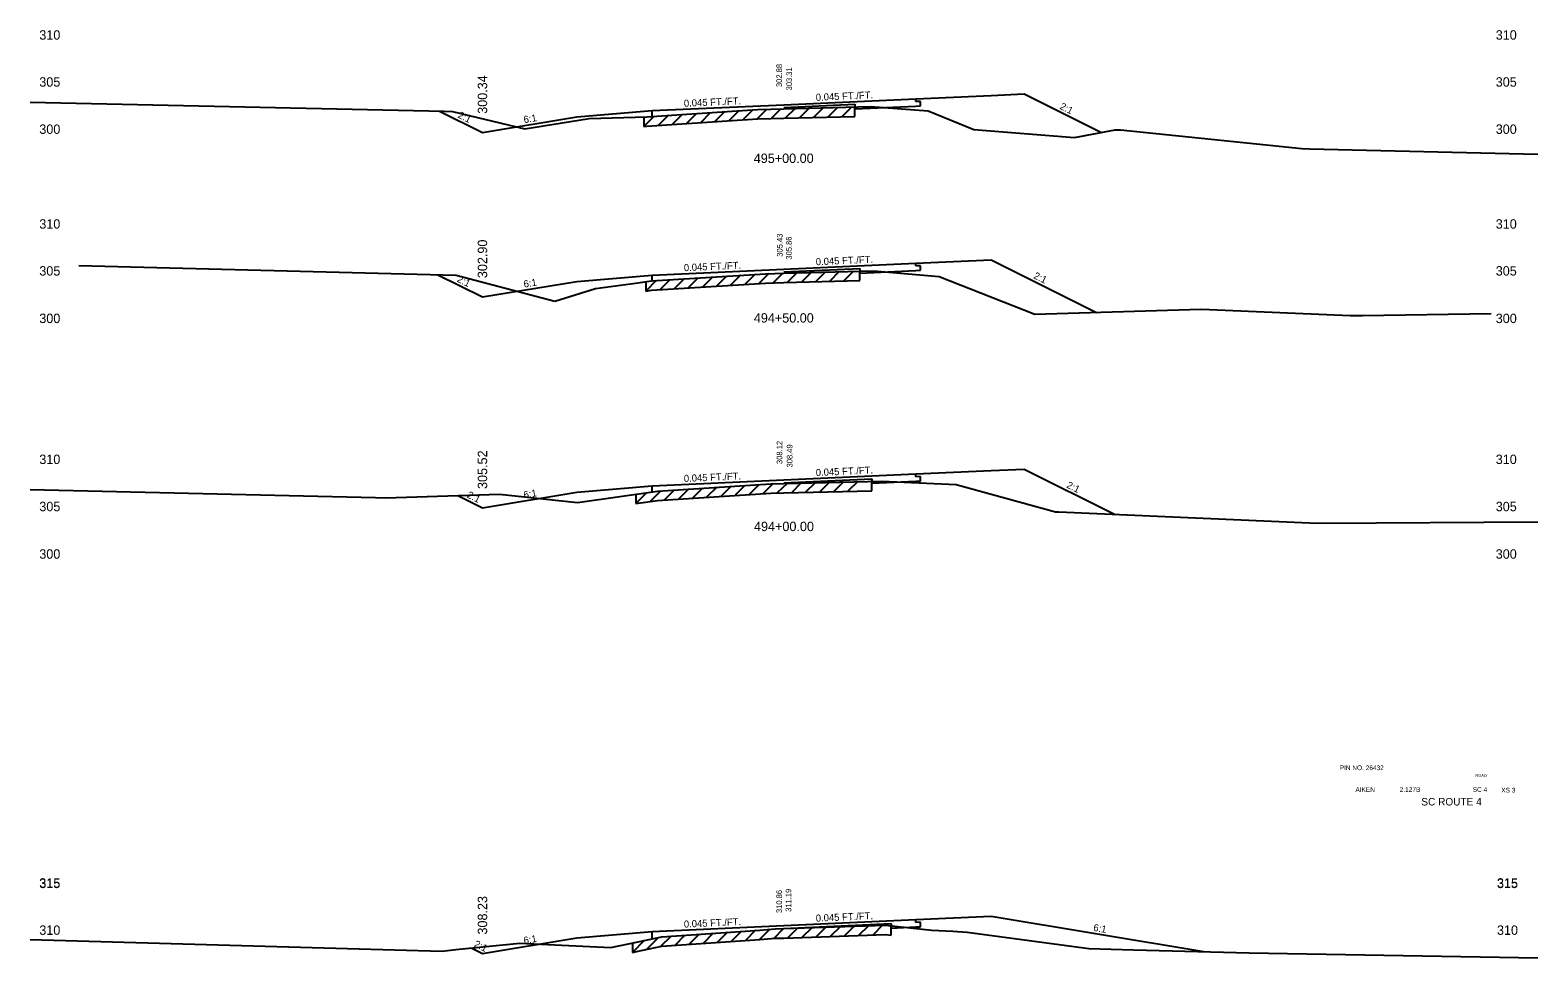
# Model space of a CAD drawing. Extents: x 883 to 1160, y 1002 to 4323.
# Drawn here: x 1000 to 1160, y 1312.8 to 1411.2 of the extents above; entities that cross this region are included whole.
import ezdxf

# ---------------------------------------------------------------- set-up
doc = ezdxf.new("R2010")
doc.units = 0
for name, color, linetype in [('Level 1', 7, 'Continuous'), ('Level 10', 7, 'Continuous'), ('Level 11', 7, 'Continuous'), ('Level 12', 7, 'Continuous'), ('Level 3', 7, 'Continuous'), ('Level 32', 7, 'Continuous'), ('Level 33', 7, 'Continuous'), ('Level 53', 7, 'Continuous'), ('Level 59', 7, 'Continuous'), ('Level 6', 7, 'Continuous'), ('Level 60', 7, 'Continuous'), ('Level 61', 7, 'Continuous'), ('Level 7', 7, 'Continuous')]:
    doc.layers.add(name, color=color, linetype=linetype)

msp = doc.modelspace()

# ---------------------------------------------------------------- linework, layer by layer
at = {"layer": 'Level 11'}
for p, q in [((1094, 1403.64), (1094, 1403.94)), ((1094.5, 1403.66), (1094, 1403.64)), ((1094.5, 1403.18), (1094.5, 1403.66)), ((1066, 1402.06), (1066, 1402.68)), ((1094, 1403.16), (1094.5, 1403.18)), ((1094, 1386.19), (1094, 1386.49)), ((1094.5, 1386.21), (1094, 1386.19)), ((1094, 1385.71), (1094.5, 1385.73)), ((1094.5, 1385.73), (1094.5, 1386.21)), ((1066, 1384.61), (1066, 1385.23)), ((1094, 1363.82), (1094, 1364.12)), ((1094.5, 1363.84), (1094, 1363.82)), ((1094, 1363.34), (1094.5, 1363.36)), ((1094.5, 1363.36), (1094.5, 1363.84)), ((1066, 1362.21), (1066, 1362.86)), ((1094, 1316.52), (1094, 1316.82)), ((1066, 1314.77), (1066, 1315.56)), ((1094.5, 1316.54), (1094, 1316.52)), ((1094, 1316.04), (1094.5, 1316.06)), ((1094.5, 1316.06), (1094.5, 1316.54))]:
    msp.add_line(p, q, dxfattribs=at)
at = {"layer": 'Level 12'}
for p, q in [((1087.51, 1402.87), (1094, 1403.16)), ((1087.51, 1403.07), (1087.51, 1402.87)), ((1088.03, 1385.44), (1094, 1385.71)), ((1088.03, 1385.65), (1088.03, 1385.44)), ((1089.31, 1363.34), (1089.31, 1363.13)), ((1089.31, 1363.13), (1094, 1363.34)), ((1091.36, 1316.16), (1091.36, 1315.92)), ((1091.36, 1315.92), (1094, 1316.04))]:
    msp.add_line(p, q, dxfattribs=at)
at = {"layer": 'Level 53'}
for p, q in [((1080, 1403.01), (1087.51, 1403.35)), ((1087.51, 1403.35), (1087.51, 1403.07)), ((1080, 1385.56), (1088.03, 1385.92)), ((1088.03, 1385.92), (1088.03, 1385.65)), ((1080, 1363.19), (1089.31, 1363.61)), ((1089.31, 1363.61), (1089.31, 1363.34)), ((1080, 1315.89), (1091.36, 1316.4)), ((1091.36, 1316.4), (1091.36, 1316.16))]:
    msp.add_line(p, q, dxfattribs=at)
at = {"layer": 'Level 59'}
for p, q in [((1066, 1402.68), (1080, 1403.31)), ((1080, 1403.31), (1094, 1403.94)), ((1066, 1385.23), (1080, 1385.86)), ((1080, 1385.86), (1094, 1386.49)), ((1066, 1362.86), (1080, 1363.49)), ((1080, 1363.49), (1094, 1364.12)), ((1080, 1316.19), (1094, 1316.82)), ((1066, 1315.56), (1080, 1316.19))]:
    msp.add_line(p, q, dxfattribs=at)
at = {"layer": 'Level 6'}
for p, q in [((1094, 1403.94), (1102, 1404.3)), ((1102, 1404.3), (1105.5, 1404.46)), ((1058, 1402.01), (1066, 1402.68)), ((1094, 1386.49), (1102, 1386.85)), ((1058, 1384.56), (1066, 1385.23)), ((1094, 1364.12), (1102, 1364.48)), ((1102, 1364.48), (1105.5, 1364.64)), ((1058, 1362.19), (1066, 1362.86)), ((1094, 1316.82), (1102, 1317.18)), ((1058, 1314.89), (1066, 1315.56))]:
    msp.add_line(p, q, dxfattribs=at)
at = {"layer": 'Level 60'}
for p, q in [((1000, 1403.58), (1043.93, 1402.62)), ((1043.93, 1402.62), (1044.82, 1402.57)), ((1044.82, 1402.57), (1052.51, 1400.75)), ((1052.51, 1400.75), (1059.32, 1401.83)), ((1059.32, 1401.83), (1065.44, 1402.02)), ((1065.44, 1402.02), (1075.04, 1402.66)), ((1075.04, 1402.66), (1077.22, 1402.8)), ((1077.22, 1402.8), (1080, 1402.88)), ((1080, 1402.88), (1089.19, 1403.11)), ((1089.19, 1403.11), (1095.29, 1402.67)), ((1095.29, 1402.67), (1100.15, 1400.67)), ((1100.15, 1400.67), (1110.82, 1399.84)), ((1110.82, 1399.84), (1115.14, 1400.63)), ((1115.14, 1400.63), (1115.71, 1400.65)), ((1115.71, 1400.65), (1134.97, 1398.67)), ((1134.97, 1398.67), (1135.76, 1398.64)), ((1135.76, 1398.64), (1160, 1398.05)), ((1005.18, 1386.24), (1045.2, 1385.21)), ((1080, 1385.43), (1089.51, 1385.69)), ((1089.51, 1385.69), (1096.47, 1385.06)), ((1045.2, 1385.21), (1055.69, 1382.45)), ((1060, 1383.81), (1064.24, 1384.38)), ((1064.24, 1384.38), (1065.93, 1384.61)), ((1065.93, 1384.61), (1078.04, 1385.37)), ((1078.04, 1385.37), (1080, 1385.43)), ((1096.47, 1385.06), (1106.61, 1381.06)), ((1055.69, 1382.45), (1060, 1383.81)), ((1106.61, 1381.06), (1124.24, 1381.62)), ((1124.24, 1381.62), (1125.15, 1381.58)), ((1125.15, 1381.58), (1140.1, 1380.93)), ((1140.1, 1380.93), (1141.4, 1380.93)), ((1141.4, 1380.93), (1155.03, 1381.13)), ((1080, 1363.12), (1090.37, 1363.36)), ((1090.37, 1363.36), (1098.28, 1363)), ((1000, 1362.48), (1036.65, 1361.62)), ((1036.65, 1361.62), (1037.73, 1361.59)), ((1037.73, 1361.59), (1049.82, 1361.96)), ((1049.82, 1361.96), (1058.07, 1361.07)), ((1058.07, 1361.07), (1066.59, 1362.3)), ((1066.59, 1362.3), (1078.61, 1363.08)), ((1078.61, 1363.08), (1080, 1363.12)), ((1098.28, 1363), (1108.81, 1360.09)), ((1108.81, 1360.09), (1109.15, 1360.08)), ((1109.15, 1360.08), (1135.76, 1358.93)), ((1135.76, 1358.93), (1137.1, 1358.91)), ((1137.1, 1358.91), (1160, 1359.04)), ((1067.05, 1314.99), (1077.42, 1315.71)), ((1077.42, 1315.71), (1079.05, 1315.83)), ((1079.05, 1315.83), (1080, 1315.86)), ((1080, 1315.86), (1090.77, 1316.22)), ((1090.77, 1316.22), (1095.69, 1315.71)), ((1095.69, 1315.71), (1097.9, 1315.58)), ((1097.9, 1315.58), (1099.45, 1315.49)), ((1099.45, 1315.49), (1109.2, 1314.18)), ((1000, 1314.7), (1038.67, 1313.62)), ((1038.67, 1313.62), (1043.72, 1313.48)), ((1043.72, 1313.48), (1045.19, 1313.63)), ((1045.19, 1313.63), (1051.95, 1314.3)), ((1051.95, 1314.3), (1061.63, 1313.87)), ((1061.63, 1313.87), (1064.36, 1314.43)), ((1064.36, 1314.43), (1067.05, 1314.99)), ((1109.2, 1314.18), (1112.36, 1313.75)), ((1112.36, 1313.75), (1117.1, 1313.62)), ((1117.1, 1313.62), (1129.35, 1313.29)), ((1129.35, 1313.29), (1160, 1312.76))]:
    msp.add_line(p, q, dxfattribs=at)
at = {"layer": 'Level 61'}
for p, q in [((1066.2, 1402.07), (1065.14, 1401.01)), ((1065.14, 1402.01), (1065.14, 1401.01)), ((1065.44, 1401.02), (1075.04, 1401.66)), ((1067.71, 1402.17), (1066.64, 1401.1)), ((1069.21, 1402.27), (1068.14, 1401.2)), ((1070.71, 1402.37), (1069.64, 1401.3)), ((1072.21, 1402.47), (1071.14, 1401.4)), ((1073.71, 1402.57), (1072.64, 1401.5)), ((1075.21, 1402.67), (1074.14, 1401.6)), ((1075.04, 1401.66), (1077.22, 1401.8)), ((1076.71, 1402.77), (1075.64, 1401.7)), ((1078.17, 1402.83), (1077.14, 1401.8)), ((1077.22, 1401.8), (1080, 1401.88)), ((1079.67, 1402.87), (1078.64, 1401.84)), ((1080, 1401.88), (1087.51, 1402.07)), ((1081.17, 1402.91), (1080.14, 1401.88)), ((1082.67, 1402.94), (1081.64, 1401.92)), ((1084.17, 1402.98), (1083.14, 1401.96)), ((1085.67, 1403.02), (1084.64, 1401.99)), ((1087.17, 1403.06), (1086.14, 1402.03)), ((1087.51, 1402.07), (1087.51, 1403.07)), ((1065.14, 1401.01), (1065.44, 1401.02)), ((1087.37, 1385.63), (1086.34, 1384.6)), ((1088.03, 1384.65), (1088.03, 1385.65)), ((1066.45, 1384.64), (1065.34, 1383.53)), ((1065.34, 1384.53), (1065.34, 1383.53)), ((1065.93, 1383.61), (1078.04, 1384.37)), ((1067.9, 1384.73), (1066.84, 1383.67)), ((1069.4, 1384.83), (1068.34, 1383.76)), ((1070.9, 1384.92), (1069.84, 1383.86)), ((1072.4, 1385.02), (1071.34, 1383.95)), ((1073.9, 1385.11), (1072.84, 1384.05)), ((1075.4, 1385.21), (1074.34, 1384.14)), ((1076.9, 1385.3), (1075.84, 1384.23)), ((1078.39, 1385.38), (1077.34, 1384.33)), ((1078.04, 1384.37), (1080, 1384.43)), ((1079.87, 1385.42), (1078.84, 1384.4)), ((1080, 1384.43), (1088.03, 1384.65)), ((1081.37, 1385.46), (1080.34, 1384.44)), ((1082.87, 1385.51), (1081.84, 1384.48)), ((1084.37, 1385.55), (1083.34, 1384.52)), ((1085.87, 1385.59), (1084.84, 1384.56)), ((1065.34, 1383.53), (1065.93, 1383.61)), ((1084.82, 1363.23), (1083.79, 1362.21)), ((1086.32, 1363.27), (1085.29, 1362.24)), ((1087.82, 1363.3), (1086.79, 1362.28)), ((1089.31, 1362.34), (1089.31, 1363.34)), ((1065.46, 1362.14), (1064.29, 1360.97)), ((1064.29, 1361.97), (1064.29, 1360.97)), ((1066.93, 1362.32), (1065.79, 1361.18)), ((1066.59, 1361.3), (1078.61, 1362.08)), ((1068.36, 1362.41), (1067.29, 1361.34)), ((1069.86, 1362.51), (1068.79, 1361.44)), ((1071.36, 1362.61), (1070.29, 1361.54)), ((1072.86, 1362.71), (1071.79, 1361.64)), ((1074.36, 1362.8), (1073.29, 1361.74)), ((1075.86, 1362.9), (1074.79, 1361.83)), ((1077.36, 1363), (1076.29, 1361.93)), ((1078.85, 1363.09), (1077.79, 1362.03)), ((1078.61, 1362.08), (1080, 1362.12)), ((1080.32, 1363.12), (1079.29, 1362.1)), ((1080, 1362.12), (1089.31, 1362.34)), ((1081.82, 1363.16), (1080.79, 1362.13)), ((1083.32, 1363.19), (1082.29, 1362.17)), ((1064.29, 1360.97), (1066.59, 1361.3)), ((1070.99, 1315.26), (1069.91, 1314.19)), ((1072.49, 1315.37), (1071.41, 1314.29)), ((1073.99, 1315.47), (1072.91, 1314.4)), ((1075.49, 1315.58), (1074.41, 1314.5)), ((1076.99, 1315.68), (1075.91, 1314.61)), ((1078.49, 1315.79), (1077.41, 1314.71)), ((1079.95, 1315.86), (1078.91, 1314.82)), ((1080, 1314.86), (1090.77, 1315.22)), ((1081.45, 1315.91), (1080.41, 1314.87)), ((1082.95, 1315.96), (1081.91, 1314.93)), ((1084.45, 1316.01), (1083.41, 1314.98)), ((1085.95, 1316.06), (1084.91, 1315.03)), ((1087.45, 1316.11), (1086.41, 1315.08)), ((1088.95, 1316.16), (1087.91, 1315.13)), ((1090.45, 1316.21), (1089.41, 1315.18)), ((1090.77, 1315.22), (1091.36, 1315.16)), ((1091.36, 1315.16), (1091.36, 1316.16)), ((1065.17, 1314.6), (1063.91, 1313.34)), ((1063.91, 1314.34), (1063.91, 1313.34)), ((1064.36, 1313.43), (1067.05, 1313.99)), ((1066.67, 1314.91), (1065.41, 1313.65)), ((1068.01, 1315.06), (1066.91, 1313.96)), ((1067.05, 1313.99), (1077.42, 1314.71)), ((1069.49, 1315.16), (1068.41, 1314.08)), ((1077.42, 1314.71), (1079.05, 1314.83)), ((1079.05, 1314.83), (1080, 1314.86)), ((1063.91, 1313.34), (1064.36, 1313.43))]:
    msp.add_line(p, q, dxfattribs=at)
at = {"layer": 'Level 7'}
for p, q in [((1105.5, 1404.46), (1113.68, 1400.36)), ((1043.43, 1402.63), (1048, 1400.34)), ((1048, 1400.34), (1058, 1402.01)), ((1102, 1386.85), (1113.17, 1381.27)), ((1043.27, 1385.26), (1048, 1382.9)), ((1048, 1382.9), (1058, 1384.56)), ((1105.5, 1364.64), (1115.13, 1359.82)), ((1045.4, 1361.82), (1048, 1360.52)), ((1048, 1360.52), (1058, 1362.19)), ((1102, 1317.18), (1124.54, 1313.42)), ((1046.86, 1313.79), (1048, 1313.23)), ((1048, 1313.23), (1058, 1314.89))]:
    msp.add_line(p, q, dxfattribs=at)

# ---------------------------------------------------------------- texts
at = {"layer": 'Level 1'}
for s, height, p in [('495+00.00', 1, (1076.79, 1397.12)), ('494+50.00', 1, (1076.8, 1380.18)), ('494+00.00', 1, (1076.82, 1358.05)), ('PIN NO. 26432', 0.5, (1138.97, 1332.68)), ('AIKEN', 0.5, (1140.64, 1330.37)), (' 2.127B', 0.5, (1145.15, 1330.37)), ('SC ROUTE 4', 0.8, (1147.63, 1328.93)), ('SC 4', 0.5, (1153.09, 1330.37)), ('XS 3', 0.5, (1156.12, 1330.31))]:
    msp.add_text(s, height=height, dxfattribs=at).set_placement(p)
at = {"layer": 'Level 10'}
for s, p in [('302.88', (1079.79, 1405.18)), ('305.43', (1079.85, 1387.17)), ('308.12', (1079.82, 1365.17)), ('310.86', (1079.79, 1317.51))]:
    msp.add_text(s, height=0.6, rotation=90, dxfattribs=at).set_placement(p)
at = {"layer": 'Level 3'}
for s, height, p in [(' 310', 1, (1000.6, 1410.21)), (' 310', 1, (1155.16, 1410.21)), (' 305', 1, (1000.6, 1405.22)), (' 305', 1, (1155.16, 1405.22)), (' 300', 1, (1000.6, 1400.21)), (' 300', 1, (1155.16, 1400.21)), (' 310', 1, (1000.6, 1390.15)), (' 310', 1, (1155.16, 1390.15)), (' 305', 1, (1000.6, 1385.17)), (' 305', 1, (1155.16, 1385.17)), (' 300', 1, (1000.6, 1380.13)), (' 300', 1, (1155.16, 1380.13)), (' 310', 1, (1000.6, 1365.17)), (' 310', 1, (1155.16, 1365.17)), (' 305', 1, (1000.6, 1360.16)), (' 305', 1, (1155.16, 1360.16)), (' 300', 1, (1000.6, 1355.12)), (' 300', 1, (1155.16, 1355.12)), ('ROAD', 0.3, (1153.38, 1331.96)), (' 315', 1, (1000.6, 1320.21)), (' 315', 1, (1000.6, 1320.16)), (' 315', 1, (1155.29, 1320.21)), (' 315', 1, (1155.29, 1320.16)), (' 310', 1, (1000.6, 1315.2)), (' 310', 1, (1155.29, 1315.2))]:
    msp.add_text(s, height=height, dxfattribs=at).set_placement(p)
at = {"layer": 'Level 32'}
for s, rotation, p in [('0.045 FT./FT.', 2.5766, (1069.39, 1403.08)), ('0.045 FT./FT.', 2.5766, (1083.39, 1403.71)), ('2:1', 333.435, (1109.2, 1402.89)), ('2:1', 333.435, (1045.32, 1401.97)), ('6:1', 9.4623, (1052.43, 1401.34)), ('0.045 FT./FT.', 2.5766, (1083.39, 1386.26)), ('0.045 FT./FT.', 2.5766, (1069.39, 1385.63)), ('2:1', 333.435, (1045.24, 1384.56)), ('6:1', 9.4623, (1052.43, 1383.89)), ('2:1', 333.435, (1106.42, 1384.92)), ('0.045 FT./FT.', 2.5766, (1083.39, 1363.89)), ('0.045 FT./FT.', 2.5766, (1069.39, 1363.26)), ('2:1', 333.435, (1109.92, 1362.7)), ('2:1', 333.435, (1046.3, 1361.65)), ('6:1', 9.4623, (1052.43, 1361.52)), ('0.045 FT./FT.', 2.5766, (1069.39, 1315.96)), ('0.045 FT./FT.', 2.5766, (1083.39, 1316.59)), ('6:1', 350.5377, (1112.79, 1315.63)), ('2:1', 333.435, (1047.04, 1313.99)), ('6:1', 9.4623, (1052.43, 1314.22))]:
    msp.add_text(s, height=0.75, rotation=rotation, dxfattribs=at).set_placement(p)
at = {"layer": 'Level 33'}
for s, p in [('300.34', (1048.5, 1402.34)), ('302.90', (1048.5, 1384.9)), ('305.52', (1048.5, 1362.52)), ('308.23', (1048.5, 1315.23))]:
    msp.add_text(s, height=1, rotation=90, dxfattribs=at).set_placement(p)
at = {"layer": 'Level 59'}
for s, p in [(' 303.31', (1080.84, 1404.6)), (' 305.86', (1080.82, 1386.64)), (' 308.49', (1080.9, 1364.58)), (' 311.19', (1080.77, 1317.42))]:
    msp.add_text(s, height=0.6, rotation=90, dxfattribs=at).set_placement(p)

doc.saveas('drawing.dxf')
